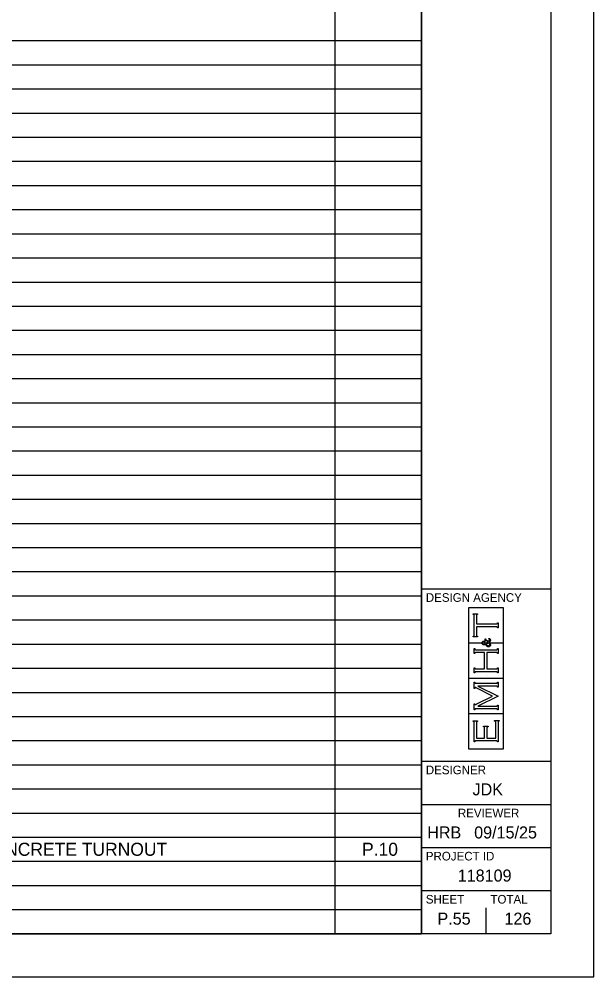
# Model space of a CAD drawing. Extents: x 0 to 34, y 0 to 22.
# Drawn here: x 27.33 to 34, y 0 to 11.11 of the extents above; entities that cross this region are included whole.
import ezdxf

# ---------------------------------------------------------------- set-up
doc = ezdxf.new("R2010")
doc.units = 0
for name, color, linetype in [('SH_Border', 7, 'Continuous'), ('SH_Cut_Line', 7, 'Continuous'), ('SH_Data', 7, 'Continuous'), ('SH_Text', 7, 'Continuous')]:
    doc.layers.add(name, color=color, linetype=linetype)

msp = doc.modelspace()

# ---------------------------------------------------------------- linework, layer by layer
at = {"layer": 'SH_Border'}
for p, q in [((32, 0.5), (32, 21.5)), ((32, 4.5), (33.5, 4.5)), ((32, 2.5), (33.5, 2.5)), ((32, 2), (33.5, 2)), ((32, 1.5), (33.5, 1.5)), ((32, 1), (33.5, 1))]:
    msp.add_line(p, q, dxfattribs=at)
msp.add_lwpolyline([(1.5, 21.5), (33.5, 21.5), (33.5, 0.5), (1.5, 0.5)], close=True, dxfattribs=at)
at = {"layer": 'SH_Cut_Line'}
msp.add_lwpolyline([(0, 0), (34, 0), (34, 22), (0, 22)], close=True, dxfattribs=at)
at = {"layer": 'SH_Data'}
for p, q in [((32.952, 4.279), (32.547, 4.279)), ((32.547, 4.279), (32.547, 3.875)), ((32.952, 3.875), (32.952, 4.279)), ((32.598, 4.204), (32.598, 4.211)), ((32.598, 4.211), (32.65, 4.211)), ((32.603, 4.203), (32.598, 4.204)), ((32.606, 4.201), (32.603, 4.203)), ((32.608, 4.199), (32.606, 4.201)), ((32.61, 4.196), (32.608, 4.199)), ((32.611, 4.192), (32.61, 4.196)), ((32.611, 4.187), (32.611, 4.192)), ((32.611, 3.968), (32.611, 4.187)), ((32.638, 4.196), (32.637, 4.192)), ((32.637, 4.192), (32.637, 4.187)), ((32.637, 4.187), (32.637, 4.093)), ((32.64, 4.199), (32.638, 4.196)), ((32.642, 4.201), (32.64, 4.199)), ((32.645, 4.203), (32.642, 4.201)), ((32.65, 4.204), (32.645, 4.203)), ((32.65, 4.211), (32.65, 4.204)), ((32.637, 4.093), (32.864, 4.093)), ((32.864, 4.061), (32.637, 4.061)), ((32.637, 4.061), (32.637, 3.968)), ((32.864, 4.093), (32.869, 4.093)), ((32.87, 4.061), (32.864, 4.061)), ((32.869, 4.093), (32.873, 4.094)), ((32.874, 4.06), (32.87, 4.061)), ((32.873, 4.094), (32.876, 4.096)), ((32.876, 4.059), (32.874, 4.06)), ((32.876, 4.096), (32.878, 4.097)), ((32.878, 4.057), (32.876, 4.059)), ((32.878, 4.097), (32.88, 4.101)), ((32.88, 4.053), (32.878, 4.057)), ((32.88, 4.101), (32.881, 4.106)), ((32.881, 4.048), (32.88, 4.053)), ((32.881, 4.106), (32.888, 4.106)), ((32.888, 4.048), (32.881, 4.048)), ((32.888, 4.106), (32.888, 4.048)), ((32.598, 3.95), (32.603, 3.951)), ((32.598, 3.944), (32.598, 3.95)), ((32.65, 3.944), (32.598, 3.944)), ((32.603, 3.951), (32.606, 3.953)), ((32.606, 3.953), (32.608, 3.955)), ((32.608, 3.955), (32.61, 3.958)), ((32.61, 3.958), (32.611, 3.962)), ((32.611, 3.962), (32.611, 3.968)), ((32.637, 3.968), (32.637, 3.962)), ((32.637, 3.962), (32.638, 3.958)), ((32.638, 3.958), (32.64, 3.955)), ((32.64, 3.955), (32.642, 3.953)), ((32.642, 3.953), (32.645, 3.951)), ((32.645, 3.951), (32.65, 3.95)), ((32.65, 3.95), (32.65, 3.944)), ((32.708, 3.887), (32.711, 3.89)), ((32.711, 3.89), (32.715, 3.892)), ((32.715, 3.892), (32.72, 3.892)), ((32.72, 3.892), (32.725, 3.892)), ((32.725, 3.892), (32.729, 3.89)), ((32.729, 3.89), (32.732, 3.887)), ((32.738, 3.893), (32.738, 3.922)), ((32.738, 3.922), (32.741, 3.922)), ((32.741, 3.893), (32.738, 3.893)), ((32.741, 3.922), (32.741, 3.918)), ((32.741, 3.918), (32.742, 3.915)), ((32.742, 3.896), (32.741, 3.895)), ((32.741, 3.895), (32.741, 3.893)), ((32.742, 3.915), (32.743, 3.913)), ((32.743, 3.897), (32.742, 3.896)), ((32.743, 3.913), (32.745, 3.911)), ((32.745, 3.899), (32.743, 3.897)), ((32.745, 3.911), (32.749, 3.908)), ((32.746, 3.899), (32.745, 3.899)), ((32.748, 3.899), (32.746, 3.899)), ((32.755, 3.899), (32.748, 3.899)), ((32.749, 3.908), (32.756, 3.904)), ((32.763, 3.895), (32.755, 3.899)), ((32.756, 3.904), (32.763, 3.9)), ((32.763, 3.9), (32.77, 3.896)), ((32.772, 3.887), (32.763, 3.895)), ((32.77, 3.896), (32.776, 3.891)), ((32.776, 3.891), (32.781, 3.895)), ((32.779, 3.923), (32.781, 3.926)), ((32.782, 3.922), (32.779, 3.923)), ((32.781, 3.926), (32.787, 3.924)), ((32.781, 3.895), (32.784, 3.898)), ((32.785, 3.921), (32.782, 3.922)), ((32.784, 3.898), (32.786, 3.901)), ((32.786, 3.919), (32.785, 3.921)), ((32.788, 3.917), (32.786, 3.919)), ((32.786, 3.901), (32.788, 3.904)), ((32.787, 3.924), (32.792, 3.921)), ((32.789, 3.914), (32.788, 3.917)), ((32.788, 3.904), (32.789, 3.908)), ((32.789, 3.911), (32.789, 3.914)), ((32.789, 3.908), (32.789, 3.911)), ((32.794, 3.89), (32.791, 3.886)), ((32.792, 3.921), (32.795, 3.918)), ((32.796, 3.894), (32.794, 3.89)), ((32.795, 3.918), (32.798, 3.914)), ((32.798, 3.897), (32.796, 3.894)), ((32.798, 3.914), (32.799, 3.91)), ((32.799, 3.901), (32.798, 3.897)), ((32.799, 3.91), (32.799, 3.905)), ((32.799, 3.905), (32.799, 3.901)), ((32.547, 3.875), (32.696, 3.875)), ((32.696, 3.869), (32.547, 3.869)), ((32.547, 3.869), (32.547, 3.465)), ((32.611, 3.749), (32.611, 3.807)), ((32.611, 3.807), (32.617, 3.807)), ((32.617, 3.807), (32.619, 3.802)), ((32.619, 3.802), (32.62, 3.798)), ((32.62, 3.798), (32.623, 3.797)), ((32.623, 3.797), (32.625, 3.795)), ((32.625, 3.795), (32.629, 3.794)), ((32.629, 3.794), (32.635, 3.794)), ((32.635, 3.794), (32.864, 3.794)), ((32.696, 3.875), (32.696, 3.869)), ((32.703, 3.879), (32.705, 3.883)), ((32.703, 3.873), (32.703, 3.879)), ((32.703, 3.868), (32.703, 3.873)), ((32.705, 3.863), (32.703, 3.868)), ((32.705, 3.883), (32.708, 3.887)), ((32.708, 3.858), (32.705, 3.863)), ((32.709, 3.879), (32.708, 3.876)), ((32.708, 3.876), (32.708, 3.873)), ((32.708, 3.873), (32.708, 3.869)), ((32.708, 3.869), (32.71, 3.866)), ((32.712, 3.853), (32.708, 3.858)), ((32.712, 3.881), (32.709, 3.879)), ((32.71, 3.866), (32.712, 3.864)), ((32.714, 3.883), (32.712, 3.881)), ((32.712, 3.864), (32.715, 3.862)), ((32.718, 3.85), (32.712, 3.853)), ((32.716, 3.884), (32.714, 3.883)), ((32.715, 3.862), (32.718, 3.861)), ((32.72, 3.884), (32.716, 3.884)), ((32.718, 3.861), (32.721, 3.861)), ((32.726, 3.85), (32.718, 3.85)), ((32.724, 3.884), (32.72, 3.884)), ((32.721, 3.861), (32.723, 3.861)), ((32.723, 3.861), (32.725, 3.862)), ((32.728, 3.882), (32.724, 3.884)), ((32.725, 3.862), (32.728, 3.862)), ((32.729, 3.85), (32.726, 3.85)), ((32.731, 3.88), (32.728, 3.882)), ((32.728, 3.862), (32.731, 3.863)), ((32.731, 3.85), (32.729, 3.85)), ((32.734, 3.877), (32.731, 3.88)), ((32.731, 3.863), (32.735, 3.865)), ((32.734, 3.851), (32.731, 3.85)), ((32.732, 3.887), (32.736, 3.883)), ((32.737, 3.872), (32.734, 3.877)), ((32.737, 3.852), (32.734, 3.851)), ((32.735, 3.865), (32.74, 3.867)), ((32.736, 3.883), (32.74, 3.878)), ((32.74, 3.867), (32.737, 3.872)), ((32.741, 3.853), (32.737, 3.852)), ((32.74, 3.878), (32.744, 3.869)), ((32.746, 3.855), (32.741, 3.853)), ((32.744, 3.869), (32.754, 3.875)), ((32.752, 3.844), (32.746, 3.855)), ((32.756, 3.86), (32.751, 3.857)), ((32.751, 3.857), (32.754, 3.852)), ((32.757, 3.837), (32.752, 3.844)), ((32.754, 3.875), (32.764, 3.881)), ((32.754, 3.852), (32.757, 3.848)), ((32.761, 3.863), (32.756, 3.86)), ((32.757, 3.848), (32.761, 3.845)), ((32.763, 3.833), (32.757, 3.837)), ((32.764, 3.865), (32.761, 3.863)), ((32.761, 3.845), (32.765, 3.843)), ((32.768, 3.829), (32.763, 3.833)), ((32.764, 3.881), (32.772, 3.887)), ((32.768, 3.867), (32.764, 3.865)), ((32.765, 3.843), (32.769, 3.841)), ((32.774, 3.872), (32.768, 3.867)), ((32.774, 3.827), (32.768, 3.829)), ((32.769, 3.841), (32.773, 3.841)), ((32.773, 3.841), (32.778, 3.841)), ((32.782, 3.878), (32.774, 3.872)), ((32.779, 3.827), (32.774, 3.827)), ((32.778, 3.841), (32.782, 3.843)), ((32.785, 3.827), (32.779, 3.827)), ((32.786, 3.873), (32.782, 3.878)), ((32.782, 3.843), (32.786, 3.846)), ((32.79, 3.829), (32.785, 3.827)), ((32.791, 3.886), (32.786, 3.881)), ((32.786, 3.881), (32.791, 3.876)), ((32.788, 3.869), (32.786, 3.873)), ((32.786, 3.846), (32.789, 3.849)), ((32.79, 3.867), (32.788, 3.869)), ((32.789, 3.849), (32.791, 3.853)), ((32.791, 3.864), (32.79, 3.867)), ((32.793, 3.834), (32.79, 3.829)), ((32.791, 3.876), (32.795, 3.87)), ((32.791, 3.861), (32.791, 3.864)), ((32.791, 3.859), (32.791, 3.861)), ((32.791, 3.853), (32.791, 3.859)), ((32.797, 3.838), (32.793, 3.834)), ((32.795, 3.87), (32.797, 3.866)), ((32.797, 3.866), (32.798, 3.861)), ((32.799, 3.844), (32.797, 3.838)), ((32.798, 3.861), (32.799, 3.857)), ((32.803, 3.869), (32.799, 3.875)), ((32.799, 3.875), (32.952, 3.875)), ((32.799, 3.857), (32.799, 3.852)), ((32.799, 3.852), (32.799, 3.844)), ((32.952, 3.869), (32.803, 3.869)), ((32.864, 3.794), (32.869, 3.794)), ((32.869, 3.794), (32.873, 3.795)), ((32.873, 3.795), (32.876, 3.797)), ((32.876, 3.797), (32.878, 3.798)), ((32.878, 3.798), (32.88, 3.802)), ((32.88, 3.802), (32.881, 3.807)), ((32.881, 3.807), (32.888, 3.807)), ((32.888, 3.807), (32.888, 3.749)), ((32.952, 3.465), (32.952, 3.869)), ((32.617, 3.749), (32.611, 3.749)), ((32.618, 3.754), (32.617, 3.749)), ((32.62, 3.758), (32.618, 3.754)), ((32.623, 3.76), (32.62, 3.758)), ((32.625, 3.761), (32.623, 3.76)), ((32.629, 3.762), (32.625, 3.761)), ((32.635, 3.762), (32.629, 3.762)), ((32.732, 3.762), (32.635, 3.762)), ((32.732, 3.572), (32.732, 3.762)), ((32.864, 3.762), (32.759, 3.762)), ((32.759, 3.762), (32.759, 3.572)), ((32.87, 3.762), (32.864, 3.762)), ((32.874, 3.761), (32.87, 3.762)), ((32.876, 3.76), (32.874, 3.761)), ((32.878, 3.758), (32.876, 3.76)), ((32.88, 3.754), (32.878, 3.758)), ((32.881, 3.749), (32.88, 3.754)), ((32.888, 3.749), (32.881, 3.749)), ((32.611, 3.527), (32.611, 3.585)), ((32.611, 3.585), (32.617, 3.585)), ((32.617, 3.585), (32.619, 3.58)), ((32.619, 3.58), (32.62, 3.576)), ((32.62, 3.576), (32.623, 3.574)), ((32.623, 3.574), (32.625, 3.573)), ((32.625, 3.573), (32.629, 3.572)), ((32.629, 3.572), (32.635, 3.572)), ((32.635, 3.572), (32.732, 3.572)), ((32.759, 3.572), (32.864, 3.572)), ((32.864, 3.572), (32.87, 3.572)), ((32.87, 3.572), (32.874, 3.573)), ((32.874, 3.573), (32.876, 3.574)), ((32.876, 3.574), (32.878, 3.576)), ((32.878, 3.576), (32.88, 3.58)), ((32.88, 3.58), (32.881, 3.585)), ((32.881, 3.585), (32.888, 3.585)), ((32.888, 3.585), (32.888, 3.527)), ((32.547, 3.465), (32.952, 3.465)), ((32.952, 3.459), (32.547, 3.459)), ((32.547, 3.459), (32.547, 3.055)), ((32.617, 3.527), (32.611, 3.527)), ((32.618, 3.532), (32.617, 3.527)), ((32.62, 3.536), (32.618, 3.532)), ((32.623, 3.537), (32.62, 3.536)), ((32.625, 3.539), (32.623, 3.537)), ((32.629, 3.54), (32.625, 3.539)), ((32.635, 3.54), (32.629, 3.54)), ((32.864, 3.54), (32.635, 3.54)), ((32.75, 3.5), (32.75, 3.5)), ((32.87, 3.54), (32.864, 3.54)), ((32.874, 3.539), (32.87, 3.54)), ((32.876, 3.538), (32.874, 3.539)), ((32.878, 3.536), (32.876, 3.538)), ((32.88, 3.532), (32.878, 3.536)), ((32.881, 3.527), (32.88, 3.532)), ((32.888, 3.527), (32.881, 3.527)), ((32.952, 3.055), (32.952, 3.459)), ((32.611, 3.345), (32.611, 3.418)), ((32.611, 3.418), (32.617, 3.418)), ((32.617, 3.345), (32.611, 3.345)), ((32.617, 3.418), (32.619, 3.412)), ((32.62, 3.352), (32.617, 3.345)), ((32.619, 3.412), (32.62, 3.409)), ((32.62, 3.409), (32.623, 3.407)), ((32.622, 3.355), (32.62, 3.352)), ((32.626, 3.355), (32.622, 3.355)), ((32.623, 3.407), (32.625, 3.405)), ((32.625, 3.405), (32.629, 3.405)), ((32.629, 3.355), (32.626, 3.355)), ((32.629, 3.405), (32.635, 3.405)), ((32.633, 3.353), (32.629, 3.355)), ((32.64, 3.35), (32.633, 3.353)), ((32.635, 3.405), (32.864, 3.405)), ((32.825, 3.257), (32.64, 3.35)), ((32.864, 3.373), (32.654, 3.373)), ((32.654, 3.373), (32.888, 3.255)), ((32.864, 3.405), (32.869, 3.405)), ((32.87, 3.373), (32.864, 3.373)), ((32.869, 3.405), (32.873, 3.405)), ((32.874, 3.372), (32.87, 3.373)), ((32.873, 3.405), (32.876, 3.407)), ((32.876, 3.37), (32.874, 3.372)), ((32.876, 3.407), (32.878, 3.409)), ((32.878, 3.369), (32.876, 3.37)), ((32.878, 3.409), (32.88, 3.412)), ((32.88, 3.365), (32.878, 3.369)), ((32.88, 3.412), (32.881, 3.418)), ((32.881, 3.36), (32.88, 3.365)), ((32.881, 3.418), (32.888, 3.418)), ((32.888, 3.36), (32.881, 3.36)), ((32.888, 3.418), (32.888, 3.36)), ((32.641, 3.165), (32.825, 3.257)), ((32.888, 3.255), (32.654, 3.138)), ((32.611, 3.096), (32.611, 3.168)), ((32.611, 3.168), (32.617, 3.168)), ((32.617, 3.168), (32.62, 3.162)), ((32.62, 3.162), (32.622, 3.158)), ((32.622, 3.158), (32.626, 3.158)), ((32.626, 3.158), (32.627, 3.158)), ((32.627, 3.158), (32.633, 3.161)), ((32.633, 3.161), (32.641, 3.165)), ((32.654, 3.138), (32.864, 3.138)), ((32.864, 3.138), (32.869, 3.138)), ((32.869, 3.138), (32.873, 3.139)), ((32.873, 3.139), (32.876, 3.141)), ((32.876, 3.141), (32.878, 3.143)), ((32.878, 3.143), (32.88, 3.146)), ((32.88, 3.146), (32.881, 3.151)), ((32.881, 3.151), (32.888, 3.151)), ((32.888, 3.151), (32.888, 3.096)), ((32.547, 3.055), (32.952, 3.055)), ((32.952, 3.049), (32.547, 3.049)), ((32.547, 3.049), (32.547, 2.645)), ((32.617, 3.096), (32.611, 3.096)), ((32.618, 3.102), (32.617, 3.096)), ((32.62, 3.105), (32.618, 3.102)), ((32.623, 3.107), (32.62, 3.105)), ((32.625, 3.109), (32.623, 3.107)), ((32.629, 3.109), (32.625, 3.109)), ((32.635, 3.109), (32.629, 3.109)), ((32.864, 3.109), (32.635, 3.109)), ((32.87, 3.109), (32.864, 3.109)), ((32.874, 3.109), (32.87, 3.109)), ((32.876, 3.107), (32.874, 3.109)), ((32.878, 3.105), (32.876, 3.107)), ((32.88, 3.102), (32.878, 3.105)), ((32.881, 3.096), (32.88, 3.102)), ((32.888, 3.096), (32.881, 3.096)), ((32.952, 2.645), (32.952, 3.049)), ((32.598, 2.962), (32.598, 2.969)), ((32.598, 2.969), (32.65, 2.969)), ((32.603, 2.961), (32.598, 2.962)), ((32.606, 2.959), (32.603, 2.961)), ((32.608, 2.957), (32.606, 2.959)), ((32.61, 2.955), (32.608, 2.957)), ((32.611, 2.951), (32.61, 2.955)), ((32.611, 2.945), (32.611, 2.951)), ((32.611, 2.725), (32.611, 2.945)), ((32.64, 2.957), (32.638, 2.955)), ((32.638, 2.955), (32.638, 2.951)), ((32.638, 2.951), (32.638, 2.945)), ((32.638, 2.945), (32.638, 2.77)), ((32.642, 2.959), (32.64, 2.957)), ((32.645, 2.961), (32.642, 2.959)), ((32.65, 2.962), (32.645, 2.961)), ((32.65, 2.969), (32.65, 2.962)), ((32.719, 2.902), (32.719, 2.908)), ((32.719, 2.908), (32.772, 2.908)), ((32.724, 2.901), (32.719, 2.902)), ((32.728, 2.899), (32.724, 2.901)), ((32.729, 2.896), (32.728, 2.899)), ((32.731, 2.894), (32.729, 2.896)), ((32.732, 2.89), (32.731, 2.894)), ((32.732, 2.884), (32.732, 2.89)), ((32.76, 2.894), (32.759, 2.89)), ((32.759, 2.89), (32.759, 2.884)), ((32.761, 2.896), (32.76, 2.894)), ((32.763, 2.899), (32.761, 2.896)), ((32.767, 2.901), (32.763, 2.899)), ((32.772, 2.902), (32.767, 2.901)), ((32.772, 2.908), (32.772, 2.902)), ((32.848, 2.965), (32.848, 2.972)), ((32.848, 2.972), (32.901, 2.972)), ((32.853, 2.964), (32.848, 2.965)), ((32.857, 2.962), (32.853, 2.964)), ((32.859, 2.96), (32.857, 2.962)), ((32.86, 2.958), (32.859, 2.96)), ((32.861, 2.953), (32.86, 2.958)), ((32.861, 2.948), (32.861, 2.953)), ((32.861, 2.77), (32.861, 2.948)), ((32.889, 2.957), (32.888, 2.953)), ((32.888, 2.953), (32.888, 2.948)), ((32.888, 2.948), (32.888, 2.725)), ((32.891, 2.96), (32.889, 2.957)), ((32.892, 2.962), (32.891, 2.96)), ((32.896, 2.964), (32.892, 2.962)), ((32.901, 2.965), (32.896, 2.964)), ((32.901, 2.972), (32.901, 2.965)), ((32.732, 2.77), (32.732, 2.884)), ((32.759, 2.884), (32.759, 2.77)), ((32.617, 2.725), (32.611, 2.725)), ((32.619, 2.73), (32.617, 2.725)), ((32.62, 2.734), (32.619, 2.73)), ((32.623, 2.735), (32.62, 2.734)), ((32.625, 2.737), (32.623, 2.735)), ((32.629, 2.738), (32.625, 2.737)), ((32.635, 2.738), (32.629, 2.738)), ((32.864, 2.738), (32.635, 2.738)), ((32.638, 2.77), (32.732, 2.77)), ((32.759, 2.77), (32.861, 2.77)), ((32.87, 2.738), (32.864, 2.738)), ((32.874, 2.737), (32.87, 2.738)), ((32.876, 2.735), (32.874, 2.737)), ((32.878, 2.734), (32.876, 2.735)), ((32.88, 2.73), (32.878, 2.734)), ((32.881, 2.725), (32.88, 2.73)), ((32.888, 2.725), (32.881, 2.725)), ((32.547, 2.645), (32.952, 2.645)), ((32.75, 0.5), (32.75, 0.8)), ((32.375, 0.675), (32.375, 0.675))]:
    msp.add_line(p, q, dxfattribs=at)
at = {"layer": 'SH_Text'}
for p, q in [((30.995, 21.5), (30.995, 0.5)), ((32, 21.5), (32, 0.5)), ((1.5, 10.86), (32, 10.86)), ((1.5, 10.58), (32, 10.58)), ((1.5, 10.3), (32, 10.3)), ((1.5, 10.02), (32, 10.02)), ((1.5, 9.74), (32, 9.74)), ((1.5, 9.46), (32, 9.46)), ((1.5, 9.18), (32, 9.18)), ((1.5, 8.9), (32, 8.9)), ((1.5, 8.62), (32, 8.62)), ((1.5, 8.34), (32, 8.34)), ((1.5, 8.06), (32, 8.06)), ((1.5, 7.78), (32, 7.78)), ((1.5, 7.5), (32, 7.5)), ((1.5, 7.22), (32, 7.22)), ((1.5, 6.94), (32, 6.94)), ((1.5, 6.66), (32, 6.66)), ((1.5, 6.38), (32, 6.38)), ((1.5, 6.1), (32, 6.1)), ((1.5, 5.82), (32, 5.82)), ((1.5, 5.54), (32, 5.54)), ((1.5, 5.26), (32, 5.26)), ((1.5, 4.98), (32, 4.98)), ((1.5, 4.7), (32, 4.7)), ((1.5, 4.42), (32, 4.42)), ((1.5, 4.14), (32, 4.14)), ((1.5, 3.86), (32, 3.86)), ((1.5, 3.58), (32, 3.58)), ((1.5, 3.3), (32, 3.3)), ((1.5, 3.02), (32, 3.02)), ((1.5, 2.74), (32, 2.74)), ((1.5, 2.46), (32, 2.46)), ((1.5, 2.18), (32, 2.18)), ((1.5, 1.9), (32, 1.9)), ((1.5, 1.62), (32, 1.62)), ((1.5, 1.34), (32, 1.34)), ((1.5, 1.06), (32, 1.06)), ((1.5, 0.78), (32, 0.78)), ((1.5, 0.5), (32, 0.5))]:
    msp.add_line(p, q, dxfattribs=at)

# ---------------------------------------------------------------- texts
at = {"layer": 'SH_Data'}
for s, height, p in [('DESIGN AGENCY', 0.1, (32.05, 4.35)), ('DESIGNER', 0.1, (32.05, 2.35)), ('JDK', 0.14, (32.592, 2.105)), ('REVIEWER', 0.1, (32.422, 1.85)), ('HRB', 0.14, (32.066, 1.605)), ('09/15/25', 0.14, (32.611, 1.605)), ('PROJECT ID', 0.1, (32.05, 1.35)), ('118109', 0.14, (32.42, 1.105)), ('SHEET', 0.1, (32.05, 0.85)), ('TOTAL', 0.1, (32.8, 0.85)), ('P.55', 0.14, (32.185, 0.605)), ('126', 0.14, (32.962, 0.605))]:
    msp.add_text(s, height=height, dxfattribs=at).set_placement(p)
at = {"layer": 'SH_Text'}
for s, height, p in [('DRAINAGE STRUCTURE, MISC.:COMBINATION CURB & GUTTER CONCRETE TURNOUT', 0.15153, (20.571, 1.404)), ('P.10', 0.1515, (31.31, 1.404))]:
    msp.add_text(s, height=height, dxfattribs=at).set_placement(p)

doc.saveas('drawing.dxf')
